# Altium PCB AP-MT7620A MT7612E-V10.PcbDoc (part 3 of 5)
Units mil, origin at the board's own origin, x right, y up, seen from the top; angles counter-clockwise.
Board outline 4645.67 x 3740.16 mil, 4 copper layers (Top, Inner Layer 2, Inner Layer 3, Bottom), stack 35.4 mil thick; 603 components, 409 nets, 1850 pads, 2004 vias.
Unrouted connection lines stored in the file: 90.
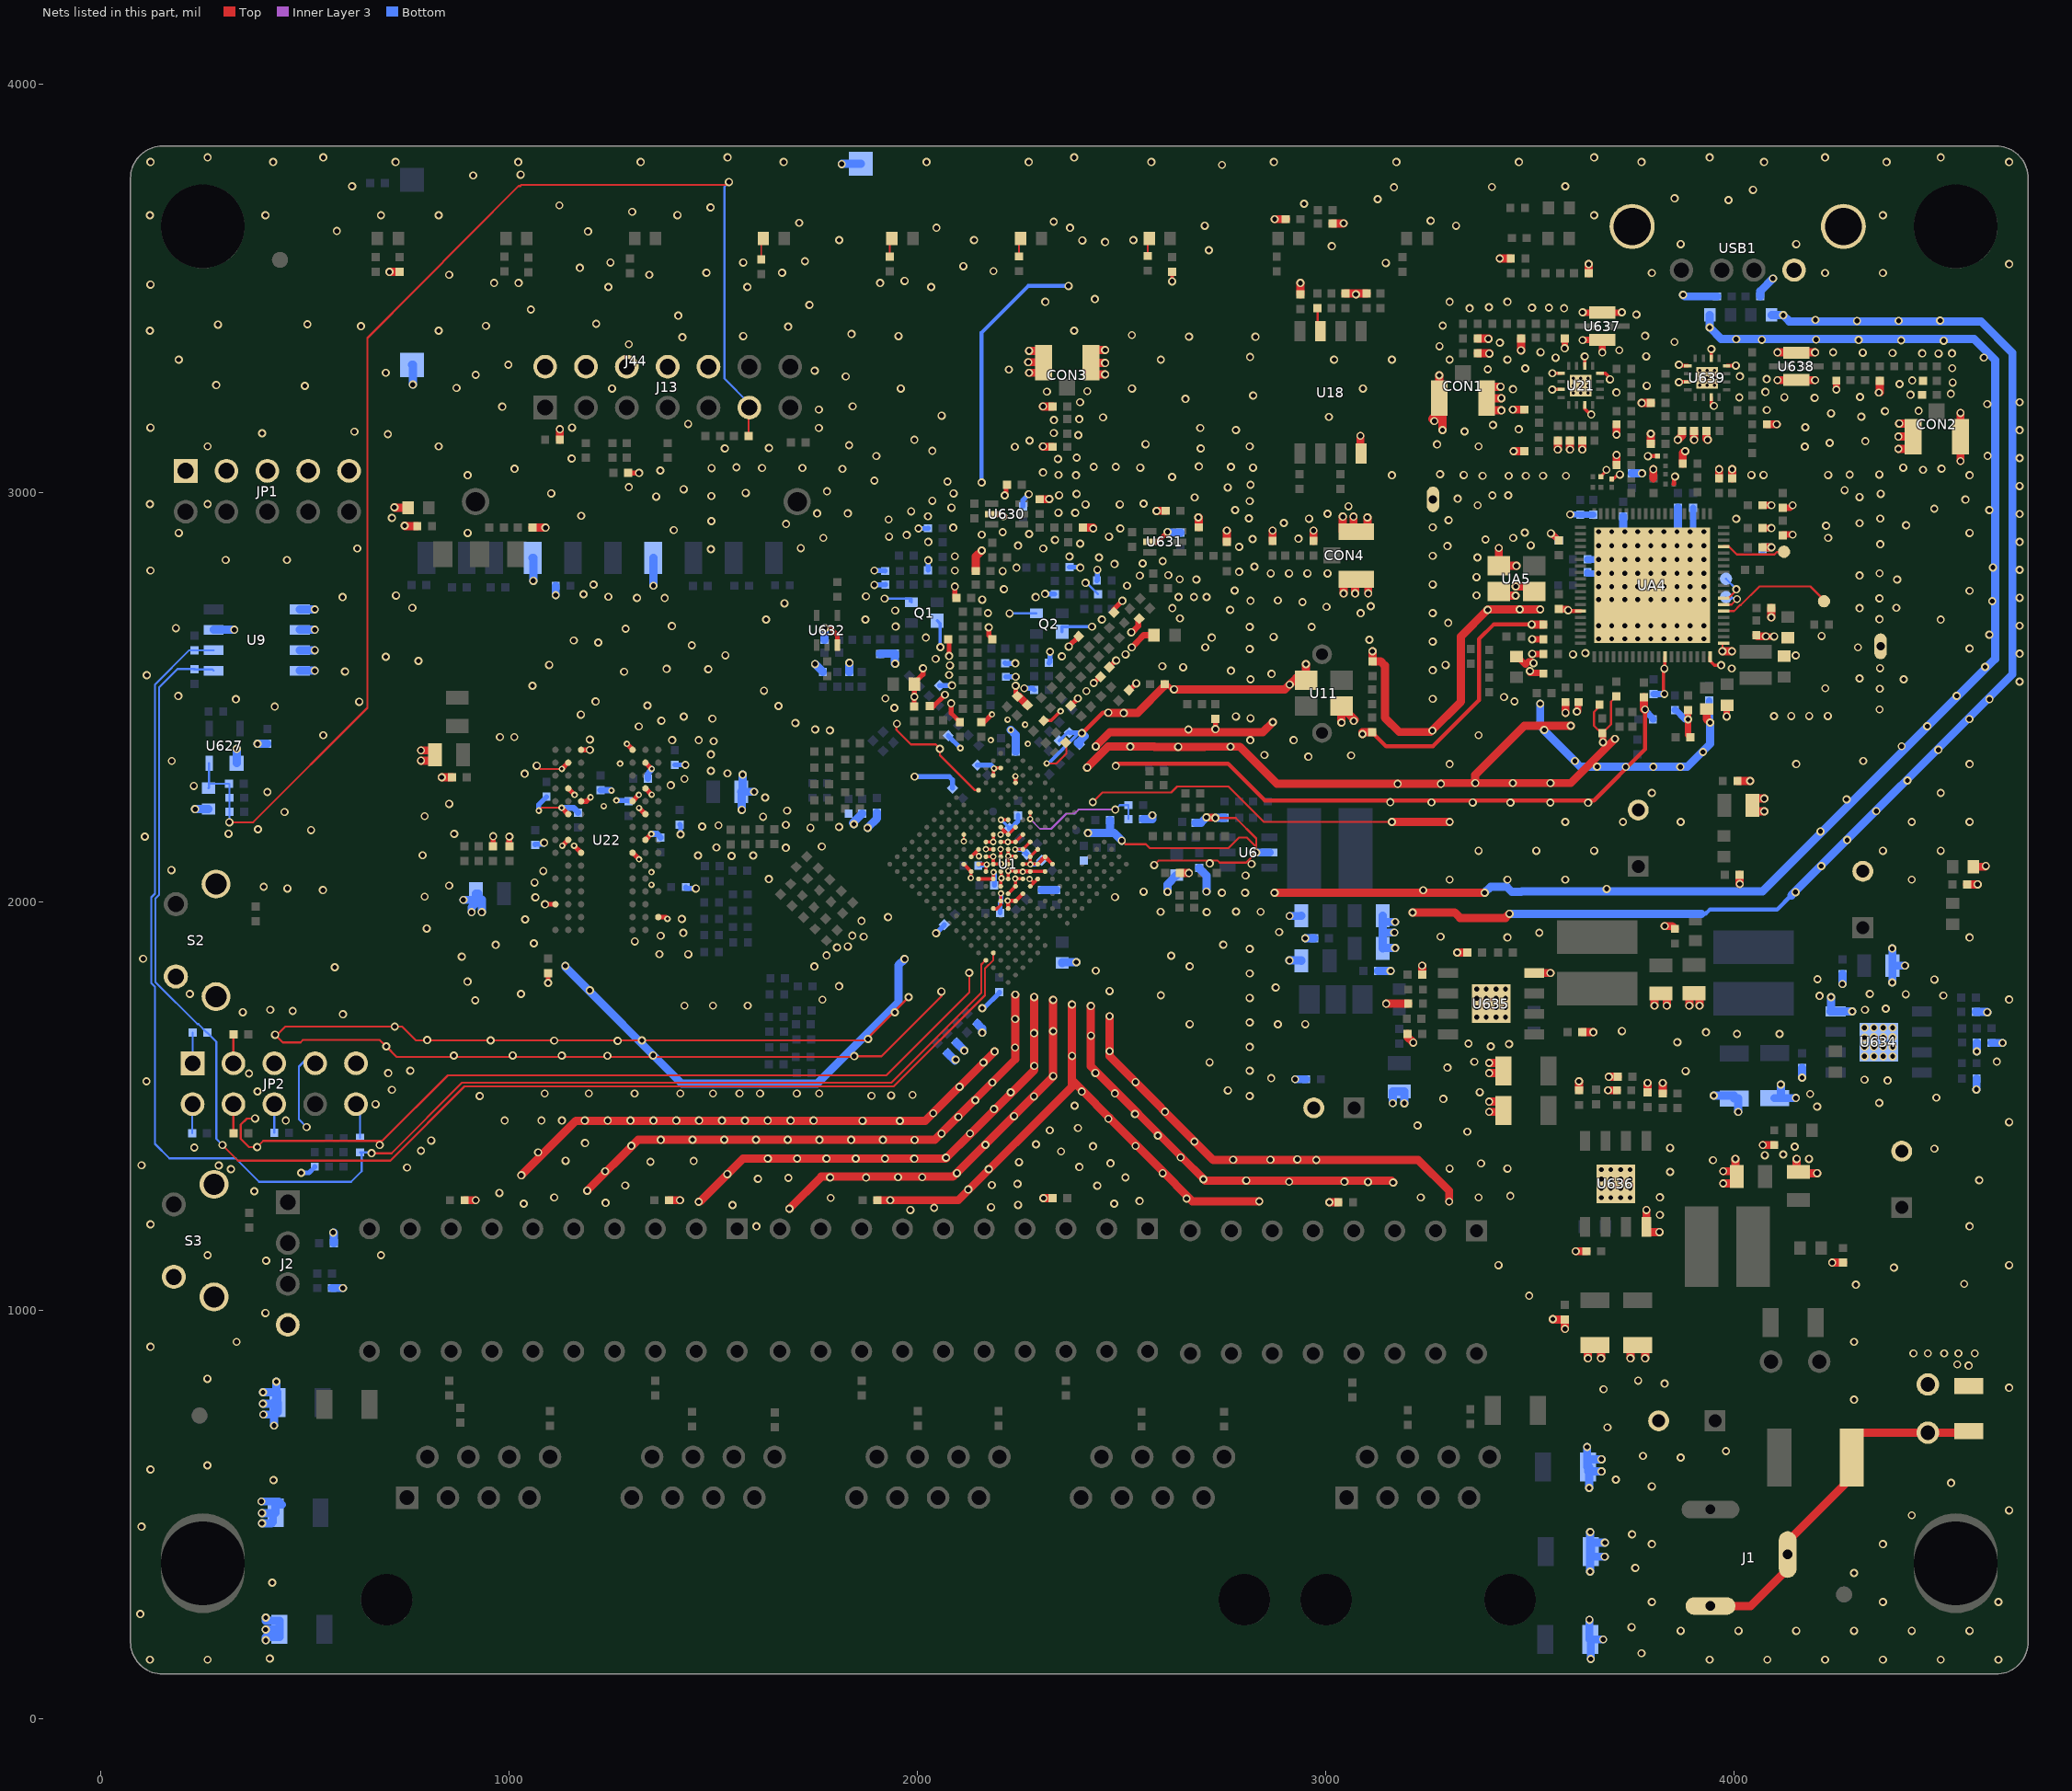
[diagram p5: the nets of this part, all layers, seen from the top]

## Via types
v1: diameter 20, hole 12, Top to Bottom, 1824 vias
v2: diameter 16, hole 8, Top to Bottom, 180 vias

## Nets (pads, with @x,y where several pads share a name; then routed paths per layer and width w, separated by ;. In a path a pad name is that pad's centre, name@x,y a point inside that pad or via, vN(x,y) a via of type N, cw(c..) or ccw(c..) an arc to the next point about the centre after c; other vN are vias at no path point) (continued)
GND: C1.2 C2.2 C7.2 C29.2 C30.2 C32.2 C33.2 C34.2 C36.2 C39.2 C40.2 C41.2 C42.2 C43.2 C44.2 C46.2 C48.2 C50.2 C51.2 C54.2 C55.2 C56.2 C57.2 C58.2 C69.1 C70.2 C72.2 C73.2 C75.2 C76.2 C77.2 C82.1 C83.2 C87.2 C88.2 C90.2 C91.2 C92.1 C93.2 C94.2 C97.2 C99.2 C100.2 C103.2 C104.2 C105.2 C107.1 C108.2 C109.1 C110.2 C111.2 C112.2 C114.2 C115.2 C116.1 C117.1 C118.1 C119.1 C120.1 C121.2 C122.1 C125.2 C128.2 C129.2 C130.2 C131.2 C132.2 C133.2 C134.2 C135.2 C136.2 C137.2 C138.2 C139.2 C140.2 C159.1 C160.1 C161.1 C162.1 C166.2 C167.2 C170.1 C182.1 C210.2 C215.2 C275.2 C456.2 C457.2 C821.2 C841.2 C842.2 C843.2 C844.2 C845.2 C846.2 C847.2 C925.2 C926.2 C928.2 C929.2 C952.2 C963.2 C964.2 C965.2 C966.2 C967.2 C968.2 C969.2 C970.2 C971.2 C973.2 C976.2 C977.1 C978.1 C979.1 C982.1 C985.2 C986.2 C987.2 C988.2 C989.2 C990.2 C991.2 C992.2 C994.2 C995.2 C996.2 C997.2 C999.1 C1000.2 C1001.1 C1004.1 C1005.1 C1007.2 C1008.2 C1016.2 C1017.2 C1018.1 C1019.1 C1020.2 C1021.2 C1022.2 C1025.2 C1026.2 C1027.1 C1028.1 C1029.1 C1030.2 C1031.2 C1032.2 C1033.2 C1035.1 C1037.2 C1038.2 C1039.1 C1040.1 C1041.2 C1042.2 C1043.2 C1045.2 C1046.1 C1048.2 C1049.2 C1051.2 C1052.2 C1061.1 C1062.1 C1063.2 CA15.2 CA16.2 CA19.2 CA20.2 CA22.2 CA24.2 CA28.2 CA32.2 CA34.2 CA35.2 CA36.2 CA37.2 CA38.2 CA39.2 CA40.2 CA41.2 CA42.2 CA43.2 CA44.2 CA45.2 CA47.2 CA48.2 CA49.2 CA50.2 CA51.2 CA52.2 CA53.2 CA54.2 CA55.2 CA56.2 CA57.2 CA58.2 CA59.2 CA60.2 CA61.2 CA62.2 CA63.2 CA64.2 CA67.2 CA68.2 CA69.2 CA70.2 CA71.2 CA72.2 CA73.2 CA74.2 CA75.1 CON1.2 CON1.3 CON2.2 CON2.3 CON3.2 CON3.3 CON4.2 CON4.3 D3.1 D4.1 J2.4 J13.2 J13.4 J13.6 J13.8 J13.10 J44.3 J44.6 J44.GND1 J44.GND2 JP1.1 JP1.3 JP1.5 JP1.7 JP1.9 JP2.5 JP2.7 JP2.9 L6.2 L9.2 L18.1 L36.2 LA11.1 LA12.1 LA13.1 LA14.1 Q1.2 Q1.4 Q2.2 Q2.4 R24.2 R42.1 R51.2 R54.2 R107.2 R126.1 R127.1 R130.1 R131.1 R134.1 R135.1 R139.1 R142.1 R159.1 R161.1 R173.1 R174.1 R176.1 R257.2 R351.2 R381.2 R477.1 R813.2 R825.2 R898.2 R943.2 R945.2 R946.2 R947.2 R950.2 R951.2 RA11.2 RA12.2 RA15.1 RC1.2 S2.2 S2.3 S2.4 S3.2 S3.3 S3.4 SHA1.1 SHA1.2 U1.C2 U1.C4 U1.D2 U1.F2 U1.F6 U1.F7 U1.F8 U1.F9 U1.F10 U1.F11 U1.F12 U1.G6 U1.G7 U1.G8 U1.G9 U1.G10 U1.G11 U1.G12 U1.H6 U1.H7 U1.H8 U1.H9 U1.H10 U1.H11 U1.H12 U1.J6 U1.J7 U1.J8 U1.J9 U1.J10 U1.J11 U1.J12 U1.K4 U1.K6 U1.K7 U1.K8 U1.K9 U1.K10 U1.K11 U1.K12 U1.L6 U1.L7 U1.L8 U1.L9 U1.L10 U1.L11 U1.L12 U1.M6 U1.M7 U1.M8 U1.M11 U1.M12 U1.N11 U6.5 U9.1 U9.2 U9.3 U9.4 U9.7 U11.2 U11.4 U18.4 U21.1 U21.3 U21.7 U21.12 U21.14 U21.17 U22.A3 U22.A7 U22.B2 U22.B8 U22.D2 U22.D8 U22.E3 U22.E7 U22.F2 U22.F8 U22.H2 U22.H8 U22.J3 U22.J7 U22.N1 U22.P9 U627.1 U630.2 U631.2 U632.3 U634.4 U634.9 U635.4 U635.9 U636.4 U636.9 U637.1 U637.3 U638.1 U638.3 U639.1 U639.3 U639.7 U639.12 U639.14 U639.17 UA4.14 UA4.31 UA4.38 UA4.39 UA4.77 UA5.1 UA5.2 UA5.4 UC1.2 UC2.2 USB1.4 USB1.5 USB1.6 | length 45986.2
  Top w4: v1(1068.5,2332.5) 1076.5,2324.5 v2(1130,2324.5) ; v2(1073.5,2222.5) 1080.5,2229.5 v2(1129.5,2229.5)
  Top w5: v1(379,1469) 359,1469 344,1454 344,1419 364,1399 v1(384,1399) 399,1414 674,1414 ; v1(684,1404) 674,1414 ; v1(1950.08,2435.08) 1949,2434 1949,2420 1984.5,2384.5 2045.09,2384.5 v1(2055.59,2374) 2055.59,2357.87 2141,2272.45 U1.F2@2150.12,2272.45 ; v1(1978.72,1766) 1930.36,1717.63 1930.36,1717.36 1873.33,1660.33 1111.32,1660.33 772.67,1660.33 739,1694 v1(721,1694) 453,1694 v1@430.5,1671.5 ; v1(2059.19,1779.88) 2059.19,1768.19 1912.51,1621.51 v1(1845.71,1621.51) 1845.71,1619.77 1009.77,1619.77 725.72,1619.77 v1(700.04,1645.45) 684.49,1661 496,1661 490,1655 447,1655 v1@430.5,1671.5 ; U1.K4@2113.93,2163.88 v2(2114,2147.5) ; v1(2127.24,1825.64) 2127.24,1777.24 1924.5,1574.5 850.7,1574.5 690.2,1414 674,1414 ; v2(2317,2338) 2341,2338 2365,2362 2365,2388 C104.2@2363.73,2388.73 ; v1(2429.89,2243.11) 2453.53,2266.75 2621.75,2266.75 2636.51,2281.51 2762.04,2281.51 2848.65,2194.9 v1(3161.99,2194.9) ; v1(2500.62,2148.92) 2509.4,2140.13 2559.76,2140.13 2568.9,2131 2762.28,2131 2787.78,2156.5 2806.83,2156.5 2830,2133.33 ; C456.2@2578.09,2652 C456.2@2579,2651.09 ; v1(2580.03,2089.45) 2590.59,2100 2735.7,2100 2740.7,2095 2805,2095 v1(2830,2120) 2830,2133.33 ; v1(2729.94,2204.56) 2779.82,2204.56 2830,2154.39 2830,2133.33 ; v1(3593.43,2712.99) 3593.43,2711.85 3623.8,2711.85 UA4.14@3623.8,2711.01 ; RA15.1@3670.36,2481.58 3670.36,2477.36 3657,2464 3657,2430 3675,2412 CA75.1@3677,2412 3698.55,2433.55 3698.55,2489.55 CA70.2@3711,2502 ; 3802,3036 3803,3036 ; v1(3971.13,2612.49) 3971.13,2632.27 UA4.39@3974.2,2632.27 ; v1@430.5,1671.5 430,1671 427,1674 v1(428,1674) v1@430.5,1671.5
  Top w8: U1.M6@2113.93,2091.5 U1.M7@2132.02,2073.4 2131,2072.38 v2(2131,2057.5) ; U1.L6@2132.02,2109.6 2142.21,2119.79 ; U1.M8@2150.12,2055.31 U1.L9@2186.31,2055.31 2186.31,2071.31 v2(2187,2072) ; U1.L7@2150.12,2091.5 2167.5,2091.5 v2(2170,2090.5) 2168.21,2087.21 U1.L8@2168.21,2073.4 ; U1.K6@2150.12,2127.69 2142.21,2119.79 ; v2(2151,2111) 2142.21,2119.79 ; v2(2168,2128) 2168.31,2127.69 U1.J7@2186.31,2127.69 ; U1.K7@2168.21,2109.6 2185.6,2109.6 v2(2186,2110) ; U1.J6@2168.21,2145.79 2185.79,2145.79 v2(2186,2146) 2186.31,2146.31 U1.H6@2186.31,2163.88 ; U1.N11@2186.31,1982.93 2187.24,1982 2194.4,1982 2204.4,1992 U1.M11@2204.4,2001.02 2204.7,2001.02 2204.7,2020 v2(2205,2020) ; U1.K8@2186.31,2091.5 2204.5,2091.5 v2(2205,2092) ; U1.D2@2186.31,2308.64 2186.31,2325.31 v2@2187.94,2325.69 ; v2(2188,2325.7) v2@2187.94,2325.69 ; v2(2204,2128) 2204.4,2127.6 U1.J8@2204.4,2109.6 ; v2(2204,2164) 2213.19,2173.19 ; U1.L10@2204.4,2037.21 2204.4,2055.4 v2(2206,2057) 2206,2071.81 U1.K9@2204.4,2073.4 ; U1.H7@2204.4,2145.79 2221.79,2145.79 v2(2222,2146) 2240.38,2146 U1.G8@2240.6,2145.79 U1.F8@2258.69,2163.88 ; U1.G6@2204.4,2181.98 2213.19,2173.19 ; U1.C2@2204.4,2326.74 2188.99,2326.74 v2@2187.94,2325.69 ; v2(2205,2200) 2222.43,2200 U1.F6@2222.5,2200.07 ; U1.L11@2222.5,2019.12 U1.K11@2240.6,2037.21 2240.6,2055.4 v2(2240,2056) 2258,2056 U1.J11@2258.69,2055.31 ; U1.K10@2222.5,2055.31 v2@2222.5,2074.5 ; U1.J9@2222.5,2091.5 2222.5,2110.5 v2(2223,2111) ; U1.H8@2222.5,2127.69 2222.5,2111.5 v2(2223,2111) ; v2(2223,2075) v2@2222.5,2074.5 ; v2(2240,2127.5) 2240.19,2127.69 U1.G9@2258.69,2127.69 U1.F9@2276.79,2145.79 ; U1.J10@2240.6,2073.4 2239.5,2074.5 v2@2222.5,2074.5 ; U1.H9@2240.6,2109.6 2239.19,2111 v2(2223,2111) ; U1.F7@2240.6,2181.98 U1.G7@2222.5,2163.88 2213.19,2173.19 ; U1.H10@2258.69,2091.5 v2@2276.79,2091.5 ; v2(2275,2055) 2275.5,2055.5 2285.29,2045.71 ; U1.J12@2276.79,2037.21 2285.29,2045.71 ; U1.H11@2276.79,2073.4 U1.G12@2312.98,2073.4 ; U1.H12@2294.88,2055.31 2285.29,2045.71 ; U1.G11@2294.88,2091.5 v2@2278,2091.5 ; U1.F10@2294.88,2127.69 U1.G10@2276.79,2109.6 v2@2276.79,2091.5 ; C842.2@2309.72,2442.62 2310.1,2443 2328,2443 v2(2351,2466) ; v1(3554.64,3253.16) U21.3@3576.26,3253.16 ; v1(3554.87,3293.11) 3554.87,3292.53 U21.1@3576.26,3292.53 ; U21.7@3633.84,3215.26 3633.84,3206.43 3648.39,3191.87 v1(3650.06,3191.87) ; U21.14@3633.84,3310.74 3633.84,3334 v1(3634,3334) ; U21.12@3671.74,3292.53 3685.09,3292.53 3697.81,3279.81 v1(3696,3278) ; C77.2@3674,3040 3674,3040.68 3673.32,3040.68 3688.14,3055.5 v1(3687.17,3056.47) ; L18.1@3700,3034 3701.86,3034 3701.86,3032.14 3717.36,3047.64 v1(3720,3045) ; v1(3829,2508) 3826.6,2510.4 3826.6,2567.6 v1(3829,2570) 3830.38,2570 3830.38,2598.8 UA4.31@3830.5,2598.8 ; v1(3864.82,3313.94) 3864.82,3311.53 U639.1@3886.26,3311.53 ; v1(3864.89,3270.86) 3864.89,3272.16 U639.3@3886.26,3272.16 ; UA4.38@3940.73,2598.8 3940.73,2589.35 3951.76,2578.32 v1(3968.02,2578.32) ; U639.7@3943.84,3234.26 3943.84,3215.53 3946.26,3213.1 v1(3950.26,3213.1) ; U639.14@3943.84,3329.74 3943.84,3351.84 v1(3944,3352) ; U639.12@3981.74,3311.53 4003.53,3311.53 v1(4004,3312) ; v2@2276.79,2091.5 v2@2277.5,2091.5 ; v2@2276.79,2091.5 2276.79,2091.21 v2(2277,2091) ; v2(2277,2091) v2@2278,2091.5 ; v2(2277,2091) v2@2277.5,2091.5 ; v2@2277.5,2091.5 v2@2278,2091.5
  Top w10: v2(2186,2110) 2186,2091.5 U1.K8@2186.31,2091.5 ; U1.M12@2222.5,1982.93 2222.5,2000.97 v2@2221.9,2001.57 ; U1.C4@2240.6,2290.55 v2@2240.55,2306.5 ; U1.J10@2240.6,2073.4 v2@2258.69,2073.4 ; U1.K12@2258.69,2019.12 U1.L12@2240.6,2001.02 2240.6,2001.57 v2@2221.9,2001.57 ; U1.H11@2276.79,2073.4 v2@2260,2073.4 ; U1.G11@2294.88,2091.5 U1.F11@2312.98,2109.6 U1.F12@2331.07,2091.5 ; v1(2403,2412) 2403.63,2411.37 2454.4,2462.13 v1(2467.89,2462.13) ; v1(2486,2332) 2491.5,2337.5 2761.16,2337.5 2851.16,2247.5 3656.5,2247.5 3781.67,2372.67 3781.67,2468 v1(3781.67,2470.04) ; v1(2624,3518) C846.2@2624,3541 ; C1061.1@3113.5,2414 3147.5,2380 3262.42,2380 3375,2492.58 3375,2642.01 3410.99,2678 v1(3504.34,2678) ; v1@3593.43,2711.85 3593.43,2711.01 UA4.14@3623.8,2711.01 ; v1(3788.76,3090) C1063.2@3812,3090 ; 3852,3022 3852.53,3022 3852.53,3040.21 v1(3855.21,3040.21) ; v2@2221.9,2001.57 2221.35,2001.57 v2(2221.35,2002.12) v2@2221.9,2001.57 ; v2@2258.69,2073.4 v2@2260,2073.4 ; v2@2258.69,2073.4 v2(2258.4,2073.12) v2@2260,2073.4
  Top w12: C125.2@961.5,2135.5 961.71,2135.5 v1(961.71,2159.62) ; v1(1088.89,1993.1) 1088.89,1993.22 1114.07,1993.22 U22.N1@1114.07,1993.34 ; v1(1096.5,1801) C132.2@1096.5,1824.5 ; v2(1129.5,2229.5) 1145.19,2213.81 U22.F2@1145.57,2213.81 ; v2(1130,2324.5) 1145.3,2339.8 U22.B2@1145.57,2339.8 ; v2(1131,2136.5) 1145.32,2150.82 U22.H2@1145.57,2150.82 ; U22.D2@1145.57,2276.8 1145.57,2276.43 v2(1161,2261) ; v2(1160,2136.5) 1177.06,2119.44 U22.J3@1177.06,2119.32 ; U22.E3@1177.06,2245.31 1190.31,2245.31 v2(1200,2255) ; U22.A3@1177.06,2371.29 1198.21,2371.29 v1(1198.5,2371) ; v2(1288.92,2385.91) 1288.8,2385.78 1303.17,2371.41 U22.A7@1303.05,2371.29 ; C845.2@1292,3049 v1(1319,3049) ; U22.J7@1303.05,2119.32 1303.18,2119.32 v2(1319,2103.5) ; U22.E7@1303.05,2245.31 1303.05,2245.55 v2(1318.5,2261) ; v2(1319,2229) 1334.19,2213.81 U22.F8@1334.54,2213.81 ; U22.H8@1334.54,2150.82 1334.54,2151.04 v2(1349,2165.5) ; U22.D8@1334.54,2276.8 1334.7,2276.8 v2(1350,2261.5) ; U22.B8@1334.54,2339.8 v2(1350,2324.5) ; U22.P9@1366.04,1961.84 1384.16,1961.84 v2(1388.5,1957.5) ; v1(1774,2669) 1787.09,2669 1804.59,2651.5 U632.3@1804.59,2627.72 ; C109.1@1992.5,2477.5 1992.5,2497 v1(1993,2501) 1993,2532.59 C457.2@1992.59,2533 ; C457.2@1992.59,2532 C457.2@1992.59,2533 ; v1(2014,2571) 2014,2556 1992.59,2534.59 C457.2@1992.59,2533 ; C107.1@2030.5,2478.5 2031,2478 2040,2478 v1(2068,2506) ; C105.2@2075.5,2641.5 2078,2637.31 v1(2078,2601) ; v1(2083,2485) 2083,2461 C844.2@2104.5,2439.5 ; v1(2092,2771) 2092,2743 C99.2@2096,2743 ; C843.2@2156.5,2439.5 2157,2439 2164,2439 v2(2183,2458) ; v1(2175,2671) 2175,2651.5 2183.5,2643 L9.2@2183.5,2641.5 ; U630.2@2182.09,2948.5 2182.09,2947.19 2211,2947.19 v1(2211,2943) ; v1(2214,2994) 2217.6,2994 2217.6,3020 C990.2@2220,3020 ; v1(2241,2528) 2241.07,2526 2241.07,2508.39 2245.23,2504.23 C110.2@2245.23,2502.23 ; v1(2371,2624) 2371,2624.45 L6.2@2395.27,2648.73 ; C82.1@2375.77,2479.23 2393,2496.46 v1(2393,2497) ; v1(2432,2535) 2447.23,2550.23 C92.1@2448.77,2550.23 ; C90.2@2470.23,2573.77 2486.46,2590 v1(2487,2590) ; C87.2@2481.27,2707.73 2481.27,2715.27 v1(2502,2736) ; C83.2@2518.23,2517.23 2518.73,2516.73 v1(2536,2534) ; C88.2@2542.25,2690.75 C88.2@2543.77,2692.27 ; U631.2@2569.09,2880.5 2569.09,2878.91 2586.9,2878.91 v1(2612.6,2904.61) ; C456.2@2579,2651.09 C456.2@2579.91,2652 ; R107.2@2606,2532 2606,2534.41 2608.41,2534.41 2626.1,2516.72 v1(2628.65,2519.27) ; v1(2730,2422) C108.2@2730,2447
  Top w15: R351.2@1001.5,2135.5 v1(1001.54,2158.91) ; v1(2524,2659) 2526,2659 2541,2674 2541,2689.5 C88.2@2542.25,2690.75 ; v1(2525.3,2622) 2526,2622 2554,2652 C456.2@2578.09,2652
  Top w16: CA43.2@3467,2599.59 3469,2599.59 3488.66,2579.93 3489.34,2579.93 3496.66,2587.25 3504.93,2587.25 v1(3508.57,2583.6) ; v1(3500,2564) 3500,2559.2 3533,2559.2 CA74.2@3533,2558 ; v1(3505.49,2642) CA50.2@3533,2642 ; v1(3505.64,2606) CA71.2@3533,2606 ; v1(3551.15,2900.9) 3552.24,2901.99 3570.62,2883.62 3570.62,2884 CA38.2@3571,2884 ; CA44.2@3571,2716 3571,2715.4 3593.43,2715.4 v1(3593.43,2712.99) ; v1(3585,3354) LA13.1@3585,3378 ; v1(3615,2465) 3618.2,2465 3618.2,2488 CA69.2@3619,2488 ; v1(3629,3374) 3629.54,3374.54 U637.1@3677,3374.54 v1(3677,3344) ; v1(3629,3442) 3629.54,3441.46 U637.3@3677,3441.46 3724.46,3441.46 v1(3725,3442) ; CA75.1@3677,2412 3678.6,2412 v1(3678.6,2389.95) ; CA63.2@3887,2468 v1(3887,2446) 3887,2408 CA64.2@3893,2402 ; v1(3981.56,2452.96) 3981.56,2480.41 CA60.2@3983,2480.41 ; CA58.2@4069,2914 v1(4091,2914) ; CA56.2@4069,2970 v1(4091,2970) ; v1(4077.62,2648.97) 4077.62,2648.91 v1(4097.87,2648.86) v1(4097.87,2648.86) ; CA57.2@4119,2896 4119,2898 v1(4143,2898) ; CA55.2@4119,2964 4137,2964 v1(4143,2970) ; v1(4250,3253) CA32.2@4250,3275
  Top w20: v1(708,3541) R159.1@733,3541 ; v1(720,2965) 721,2964 C964.2@753.41,2964 ; v1(745,2920) 746,2919 C963.2@776,2919 ; v1(785,2345) 819.55,2345 C965.2@819.55,2359 819.55,2370 v1(785,2370) ; v1(836,2304) C966.2@861,2304 ; C115.2@892,1269 v1(919,1269) ; v1(1030.8,1329.91) 1164.41,1463.52 1354,1463.52 1522,1463.52 1690,1463.52 1865.97,1463.52 2020.08,1463.52 v1(2189.45,1632.89) ; R898.2@1058,2915 v1(1090,2915) ; R477.1@1125,3130 v1(1125,3156) ; v1(1192.08,1292.41) 1316.34,1416.67 1527.39,1416.67 v1(1838.12,1416.68) 2042.78,1416.67 2240.07,1613.96 v1(2240.07,1772.13) ; C114.2@1392,1269 v1(1419,1269) ; v1(1465,1265) 1465.69,1265.69 1468.36,1265.69 1573.17,1370.5 1821.28,1370.5 2069.38,1370.5 2071.24,1372.35 2130.07,1431.18 2230.39,1531.51 2286.33,1587.45 v1(2286.33,1766.19) ; v1(1687.06,1248.17) 1765.39,1326.5 2087.61,1326.5 2332.73,1571.62 v1(2332.73,1759.21) ; C112.2@1902,1269 v1(1934,1269) 2100.52,1269 2378.75,1547.23 2378.75,1563.14 ; C100.2@2143,2809 2143,2844 v1(2158,2859) ; C110.2@2245.23,2502.23 2248.23,2502.23 C841.2@2269.73,2480.73 ; v1(2272,3320) CON3.2@2307.94,3320 ; v1(2274,3294) 2307.94,3294 CON3.2@2307.94,3320 ; v1(2274,3348) 2307.94,3348 CON3.2@2307.94,3320 ; C1048.2@2300,2984.5 2323,2984.5 v1(2323,2985) ; v1(2308,3114) 2308,3113 C973.2@2331,3113 ; v1(2308,3212) 2308,3211 C991.2@2331,3211 ; v1(2309,1274) C111.2@2331,1274 ; v1(2378.75,1747.88) 2378.75,1563.14 ; C1049.2@2405.48,2915.62 2431,2915.62 v1(2431,2913) ; v1(2416,2328) 2467.17,2379.17 v1(2521.67,2379.17) 2580.04,2379.17 2580.58,2378.63 v1(2638.95,2378.63) 2702.74,2378.63 2703.01,2378.9 v1(2766.79,2378.9) 2790,2378.9 2880.9,2288 v1(3176,2288) v1(3282,2288) 3284,2290 v1(3366,2290) ; v1(2424.92,1744.22) 2424.92,1596.97 2438.79,1583.09 2646.5,1375.38 2704.96,1316.93 3160.62,1316.93 v1(3165.19,1312.36) ; v1(2437.1,2379.85) 2472.04,2414.78 2846.34,2414.78 v1(2870.54,2438.98) ; v1(2460,3290) 2426.06,3290 CON3.3@2426.06,3318 ; v1(2460,3318) CON3.3@2426.06,3318 ; v1(2460,3350) 2426.06,3350 CON3.3@2426.06,3318 ; v1(2467.89,2462.13) 2467.89,2461.76 2505.37,2461.76 v1(2505.37,2461.4) 2539.2,2461.4 2606,2528.2 R107.2@2606,2532 ; v1(2470.98,1719.23) 2470.98,1621.34 2724.96,1367.36 v1(2976.81,1367.36) 3226.75,1367.36 3302.06,1292.05 v1(3302.06,1265.53) ; v1(2586,2956) 2586,2956.5 C1007.2@2608.5,2956.5 ; v1(2628.65,2519.27) 2900.17,2519.27 v1(2911.91,2531.01) 2927.9,2547 U11.4@2951.69,2547 ; C54.2@2643,2070 2665.04,2070 v1(2665.04,2069.67) ; v1(2688,2940) 2689,2940 C1051.2@2689,2916 ; v1(2708,2206.17) 2708,2205.67 2729.94,2205.67 v1(2729.94,2204.56) ; C1052.2@2758,2880 v1(2758,2908) ; v1(2837.32,1266.3) 2673.27,1266.3 2663.14,1276.5 2602.88,1337.24 2536.69,1403.95 2470.51,1470.66 2404.83,1536.85 2378.75,1563.14 ; C971.2@2870,2883 v1(2870,2908) ; v1(2874.73,2021.56) 3141.84,2021.56 3141.94,2021.67 v1(3389.05,2021.67) ; v1(2875,3670) C847.2@2902,3670 C847.2@2903,3670 ; C137.2@2938,3486 v1(2938,3514) ; v1(2951.5,2581) 2951.69,2579 U11.4@2951.69,2547 ; U11.4@2951.69,2541.5 U11.4@2951.69,2547 ; C970.2@2970,2883 v1(2970,2908) ; v1(3009,1264) C121.2@3031,1264 ; R134.1@3017,3659 3043,3659 v1(3044,3660) ; v1(3038.5,2438) U11.2@3038.5,2475.94 ; v1(3042,2942) 3042,2906.11 3042.06,2906.06 CON4.2@3068,2906.06 ; v1(3044,2754) 3044,2787.94 CON4.3@3072,2787.94 ; R127.1@3048,3488 v1@3074,3488 ; v1(3068,2942) CON4.2@3068,2906.06 ; v1(3068.5,2442) 3071.06,2444.56 3039.68,2475.94 U11.2@3038.5,2475.94 ; v1(3072,2754) CON4.3@3072,2787.94 ; v1(3074,3486) v1@3074,3488 ; v1(3085,3140) 3085,3096.2 U18.4@3087,3096.2 ; v1(3090,2410) 3090,2414 C1061.1@3113.5,2414 ; R135.1@3100,3488 v1@3074,3488 ; v1(3102,2940) 3102,2906.06 CON4.2@3068,2906.06 ; v1(3104,2754) 3104,2787.94 CON4.3@3072,2787.94 ; v1(3114.5,2612.38) C1062.1@3114.5,2588 3134.5,2588 3145,2577.5 3145,2450 3180,2415 3256.65,2415 3331,2489.35 3331,2648.83 3396.17,2714 v1(3396.49,2714) 3397.49,2715 v1(3475,2715) v1(3525,2715) ; v1(3147.98,1749.79) 3147.98,1750 C1035.1@3202,1750 ; v1(3161.99,2194.9) v1(3303.42,2194.9) ; C1029.1@3200,1676 3200,1668.88 3214.22,1654.66 v1(3214.33,1654.77) ; v1(3212.66,1973.23) 3315.75,1973.23 3328.97,1960 3440,1960 v1(3450,1970) ; R946.2@3236,1821 3236,1843.15 v1(3236.1,1843.15) ; v1(3266,3176) 3260.64,3181.36 3283.29,3204 CON1.3@3283.29,3232 ; CON1.3@3277.93,3232 CON1.3@3278,3232 ; v1(3278,3288) CON1.3@3278,3232 ; v1(3286,3154) 3286,3232 CON1.3@3283.29,3232 ; v1(3321.78,1875) R947.2@3347,1875 ; CA15.2@3372,3342 3400.41,3342 v1(3400.41,3341.11) ; CA16.2@3372,3378 3398.16,3378 v1(3398.16,3377.08) ; v1(3400,1485) 3434.88,1485 C1026.2@3434.88,1489 3434.88,1510 v1(3400,1510) ; v1(3400,1580) 3434.88,1580 C1025.2@3434.88,1585 3434.88,1605 v1(3400,1605) ; UA5.1@3423.69,2758.5 3423.69,2748.7 v1(3464.85,2748.7) ; v1(3423.69,2865.21) UA5.4@3423.69,2821.5 v1(3466.73,2821.5) ; v1(3426,3574) R142.1@3453,3574 ; v1(3428,3260) 3394.07,3260 CON1.2@3394.07,3232 ; v1(3430,3202) 3400,3202 3394.07,3207.93 CON1.2@3394.07,3232 ; v1(3430,3232) CON1.2@3394.07,3232 ; v1(3458,3204) R173.1@3486,3204 ; v1(3460,3102) R161.1@3486,3102 ; v1(3465.25,2771.15) 3497.66,2771.15 UA5.2@3510.31,2758.5 ; v1(3477.98,3348.98) CA28.2@3478,3378 ; v1(3504.34,2678) CA39.2@3533,2678 ; U635.4@3510.61,1825 v1(3550,1825) ; v1(3556,978) 3556,977 C2.2@3585,977 3585,954 v1(3586,954) ; v1(3568,3106) C159.1@3568,3128 ; v1(3587,2462) CA67.2@3587,2488 ; v1(3598,3106) C160.1@3598,3128 ; v1(3600,2430) 3486,2430 3366,2310 v1(3366,2290) ; v1(3612,1144) C1039.1@3638,1144 ; C1040.1@3620,1538 v1(3620,1560) ; C1028.1@3628,1680 3654.35,1680 3654.4,1680.05 3654.95,1680.05 v1(3655,1680) ; v1(3628,3106) C170.1@3628,3128 ; v1(3642,882) 3642,913.88 C1038.2@3659,913.88 3674,913.88 v1(3674,882) ; R825.2@3644,3538 v1(3644,3560) ; v1(3691,1538) C1046.1@3713,1538 ; v1(3693,1571) R950.2@3715,1571 ; v1(3708,2398) 3600,2290 v1(3550,2290) v1(3458,2290) v1(3366,2290) ; LA12.1@3712,3068 v1(3712,3092.9) ; v1(3712,3142.83) CA24.2@3712,3168 ; v1(3746,882) 3746,913.88 C1037.2@3764,913.88 3782,913.88 v1(3782,882) ; v1(3773.73,3220) R176.1@3796,3220 ; CA62.2@3779.26,2499.93 3779.26,2470.41 v1@3781.67,2468 ; v1(3785,1245) U636.4@3785,1203.39 3785,1190.89 3785.11,1191 v1(3817,1191) ; R951.2@3788,1533 v1(3788,1556) ; R174.1@3796,3120 v1(3796,3145.12) ; 3802,3036 v1(3802,3058) ; v1(3805,1745) 3805,1774.55 C1030.2@3821,1774.55 3835,1774.55 v1(3835,1745) ; C1043.2@3825,1530 v1(3825,1556) ; v1(3830,1940) 3848,1940 C1032.2@3855,1933 ; v1(3862,3130) 3872,3140 C161.1@3872,3152 ; LA11.1@3874,3072 3874,3097.93 v1(3880,3102) ; v1(3890,1745) 3890,1775.55 C1031.2@3902,1775.55 3915,1775.55 v1(3915,1745) ; v1(3902,3130) C162.1@3902,3152 ; C182.1@3932,3152 3932,3133 v1(3935,3130) ; CA68.2@3932.54,2471.63 3932.54,2446.46 v1(3941,2438) ; CA53.2@3963,3036 v1(3963,3058) ; v1(3971.13,2612.49) v1(3994.45,2612.49) ; v1(3973,1310) 4006.55,1310 C1042.2@4006.55,1327 4003,1330.55 C1042.2@4003,1340 ; v1(3973,1340) C1042.2@4003,1340 ; CA52.2@3995,3036 v1(3995,3058) ; v1(4003,1370) C1042.2@4003,1340 ; C926.2@4008,2295 v1(4039.1,2295) ; C928.2@4013,2065 4013,2042.81 v1(4013.67,2042.81) ; CA36.2@4054.14,2651.56 4056.73,2648.97 v1(4077.62,2648.97) ; CA49.2@4069,2867 v1(4091,2867) ; v1(4070,1404) C952.2@4098,1404 ; v1(4073.5,2220.71) 4044.45,2220.71 C925.2@4044.45,2235 4044.45,2251.99 v1(4073.65,2251.99) ; CA22.2@4080,3168 v1(4104,3168) ; v1(4090.68,2695.49) CA73.2@4090.68,2717.93 ; v1(4106,3276) U638.1@4152,3276 ; v1(4106,3344) U638.3@4152,3344 ; U638.1@4152,3276.54 U638.1@4152,3276 ; U638.3@4152,3343.46 U638.3@4152,3344 ; v1(4153,1370) 4153,1342.45 C1041.2@4157,1338.45 4160.45,1335 v1(4203,1335) ; v1(4198,3276) U638.1@4152,3276 ; v1(4198,3344) U638.3@4152,3344 ; v1(4240,1116) C929.2@4266,1116 ; v1(4354.26,3245.76) 4356,3245.76 LA14.1@4356,3274 ; v1(4402,3108) 4436,3108 4440,3104 4440,3135.93 CON2.3@4437.93,3138 ; v1(4402,3138) CON2.3@4437.93,3138 ; v1(4404,3170) 4430,3170 4437.93,3162.07 CON2.3@4437.93,3138 ; v1(4554,3078) 4554.07,3078.07 CON2.2@4554.07,3138 4554.07,3195.93 v1(4554,3196) ; C968.2@4570,2042 v1(4596,2042) ; C967.2@4585.59,2085 4614,2085 v1(4616,2087) ; U11.2@3038.5,2475.94 3038.31,2475.94 U11.2@3038.31,2478.5 3038.5,2478.31 U11.2@3038.5,2475.94 ; CON1.3@3278,3232 CON1.3@3283.29,3232
  Bottom w5: v1(505,1448) 486,1467 486,1596 504,1614 516,1614 JP2.7@526,1604 ; v1(2412,2780) 2414.5,2780 C1000.2@2442.5,2752
  Bottom w5.5: v1(1920,2741.5) 1980.72,2741.5 Q1.4@1980.82,2741.4 ; v1(2226,2705) 2290.91,2705 Q2.4@2291.5,2705.59 ; Q1.4@1980.82,2741.4 1985.5,2741.4 1986,2740.89 Q1.4@1986,2732.59 1981.79,2735.01 Q1.4@1980.82,2741.4
  Bottom w7.87: Q1.2@2049,2687.32 2056.46,2679.85 v1(2056.46,2622.6) ; Q2.2@2354.5,2660.32 2354.5,2672.6 v1(2427.72,2672.6)
  Bottom w8: C72.2@2149.5,2087.5 2168.5,2087.5 v2(2170,2090.5) ; v2(2205,2200) 2205.5,2200 C44.2@2225.77,2179.73 ; v2(2317,2338) 2321,2338 2395,2412 v1@2395,2413.27 ; C94.2@2347.73,2393.73 2370,2416 C994.2@2372.73,2413.27 ; CA41.2@3623,2947 CA41.2@3623,2947.33
  Bottom w10: v1(2157.7,3025.71) 2157.7,3392.57 2271.66,3506.53 v1(2370.39,3506.53) ; v2(2277,2091) 2291.14,2091 2303.07,2102.93 C39.2@2304.77,2101.23 ; 3920,1970 3930,1970 3940,1980 4105,1980 4140,2015
  Bottom w12: v1(492,1336) 511,1336 525,1350 C976.2@525,1351 ; C129.2@1064.5,2138.5 1064.5,2140.62 1086.64,2140.62 v1(1086.64,2143.79) ; v2(1073.5,2222.5) 1073.5,2237.5 C138.2@1092.5,2256.5 ; v2(1263.5,2247.5) 1291.5,2247.5 C133.2@1293.5,2245.5 ; C134.2@1406.5,2334.5 v1(1432.5,2334.5) ; C135.2@1418.5,2188.5 1420.5,2186.5 v1(1420.5,2164.5) ; C130.2@1433.5,2035.5 1433.5,2032 v1(1458,2032) ; v1(1895,2775) 1922,2775 C979.1@1922,2776 ; v1(1895,2810) 1921.5,2810 C988.2@1921.5,2809 ; v1(1993.51,2305.84) 2078.31,2305.84 2086.27,2297.87 C75.2@2086.27,2277.73 ; v1(2003,2913) 2026,2913 C989.2@2026.5,2913.5 ; C985.2@2026,2810.5 2027,2811.5 v1(2027,2835) ; v1(2046.03,1922.29) 2066.64,1942.9 C76.2@2066.27,1943.27 ; C986.2@2054.73,2528.73 v1(2085,2529) ; C215.2@2074.73,1628.27 2078.73,1628.27 v1(2094,1613) ; C987.2@2075.77,2405.77 2105.5,2376.04 v2(2105.5,2375.5) ; C93.2@2146.77,2334.23 2180.77,2334.23 v2(2188,2325.7) ; v1(2159,1739) 2164,1739 2163.49,1739.51 2201.49,1777.51 2201,1777.51 R42.1@2201,1778 ; v2(2187,2072) 2188.5,2070.5 C43.2@2188.5,2039.5 ; C41.2@2203,1972 2203,1996 2205,1998 v2(2205,2020) ; C1001.1@2215,2583.5 2215.5,2583 v1(2240,2583) ; C1004.1@2217,2550 v1(2241,2550) ; C44.2@2225.77,2179.73 2229.73,2179.73 2247,2197 C91.2@2247,2211 ; v2(2240,2127.5) 2256.55,2127.5 C40.2@2268.15,2115.89 ; C992.2@2259,2967 2259,2983 v1(2273,2997) ; v1(2262,2522) 2282.5,2522 C995.2@2286.5,2518 ; v1(2313,2753) 2335.5,2753 C999.1@2336.5,2752 ; C1005.1@2322.5,2584 2325,2586.5 v1(2325,2611.5) ; C997.2@2372.5,2818.5 2397.5,2818.5 v1(2399,2817) ; C994.2@2372.73,2413.27 2395,2413.27 2401.73,2413.27 v1(2403,2412) ; C996.2@2440,2785.5 2441,2786.5 v1(2441,2812)
  Bottom w15: v2(1129.5,2229.5) 1158.5,2229.5 1169.5,2218.5 C131.2@1169.5,2217.5 ; C140.2@1224.5,2272.5 1250.5,2272.5 v2(1251.5,2271.5) ; C128.2@1340.5,2300.5 1340.5,2312.5 v2(1350,2324.5) ; v2(1349,2165.5) 1363.5,2165.5 1371.5,2157.5 C139.2@1371.5,2156.5 ; v1(3551.15,2900.9) 3552.15,2901.91 3570.53,2883.53 3571,2883.53 CA40.2@3571,2884 ; v1(3598.62,2947.33) CA41.2@3623,2947.33 ; CA41.2@3623,2947 CA42.2@3655,2947
  Bottom w16: CA34.2@3641,2806 3641,2803 v1(3668,2803) ; CA35.2@3641,2838 3641,2837 v1(3668,2837) ; v1(3781.67,2470.04) 3780.51,2468.87 3802.19,2447.19 3802.19,2446 CA61.2@3801,2446 ; RA11.2@3803,2508 v1(3829,2508) ; RA12.2@3855,2468 3855,2469.31 3856.31,2469.31 3879.61,2446 v1(3887,2446) ; v1(3892,2905) 3899,2912 CA59.2@3899,2964 ; CA72.2@3939,2492 3939,2466 3941,2464 v1(3941,2438)
  Bottom w20: v1(232,2226) 264.59,2226 RC1.2@265,2226.41 ; U9.7@277.49,2665 v1(328,2665) ; U627.1@333.92,2338.68 334,2338.76 v1(334,2374) ; v1(385,2386) C969.2@409,2386 ; v1(394.52,531.66) 436.82,531.66 444.63,523.86 428.88,523.86 C117.1@428.88,504 C117.1@427.67,502.78 ; v1(395.89,478.02) 419.04,478.02 422.53,481.51 422.53,497.65 C117.1@427.67,502.78 ; v1(395.89,503.1) 396.2,502.78 C117.1@427.67,502.78 ; v1(398.06,770.88) C116.1@425.38,770.88 ; v1(398.53,798.82) C116.1@430.86,798.82 ; v1(399.24,744.37) C116.1@425.38,744.37 ; v1(404.84,218.09) C120.1@438.88,218.09 ; v1(404.98,247.54) 404.98,239.49 438.88,239.49 C120.1@438.88,219 C120.1@438.88,218.09 ; v1(405.13,191.98) 405.13,199.61 438.88,199.61 C120.1@438.88,218.09 ; v1(425.38,717.3) C116.1@425.38,744.37 ; v1(430.86,824.99) C116.1@430.86,798.82 ; U9.4@488.51,2565 v1(525,2565) ; U9.3@488.51,2615 v1(525,2615) ; U9.2@488.51,2665 v1(525,2665) ; U9.1@488.51,2715 v1(525,2715) ; R139.1@567,1054 v1(594,1054) ; v1(570,1190) 572,1190 R54.2@572,1164 ; J44.GND1@763.17,3313.44 765,3313.44 v1(765,3265) ; v1(889,2004) 919.55,2004 C73.2@919.55,2019 ; v1(909,1974) 909,1985.78 925.38,2002.17 C73.2@925.38,2013.17 ; v1(934,1974) 934,2004.55 C73.2@925.38,2013.17 ; J44.6@1058.45,2841 1060,2841 v1(1060,2785) ; v1(1115,2750) C275.2@1115,2773 ; v1(1138.5,1842.5) 1138.5,1839.5 1424,1554 1754.8,1554 1954,1753.2 1954,1844 v1(1969,1859) ; J44.3@1353.72,2841 1354.26,2841 v1(1354.26,2773.03) ; v1(1570.5,2224.5) 1570.5,2266.95 C136.2@1568.95,2268.5 ; v1(1572.5,2310.5) 1572.5,2272.05 C136.2@1568.95,2268.5 ; v1(1600.5,2268.5) C136.2@1568.95,2268.5 ; v1(1749.79,2581.21) R131.1@1769,2562 ; C978.1@1773,2641 1773,2668 v1(1774,2669) ; v1(1815,3805) 1815.57,3805.57 J44.GND2@1861.6,3805.57 ; R130.1@1834,2562 v1(1834,2584) ; v1(1845.06,2189.15) 1842.1,2192.1 1848.5,2198.5 C70.2@1865.5,2215.5 ; v1(1878.41,2180.16) 1901.5,2203.25 R813.2@1901.5,2217.5 ; C977.1@1909,2606 1909,2607 C982.1@1945,2607 1945,2582 v1(1946,2582) ; C215.2@2074.73,1628.27 2092,1611 v1(2094,1613) ; C57.2@2096.27,1654.27 2115.27,1635.27 v1(2115,1635) ; C58.2@2147.73,1700.27 2159,1689 v1(2159,1679) ; v2(2229,2420) 2241,2408 C103.2@2241,2400 C97.2@2241,2367.5 ; C167.2@2305,2028 C166.2@2340,2028 ; C42.2@2355,1849.41 2355,1851.58 v1(2389.47,1851.58) ; C36.2@2396.73,2384.73 2393.3,2388.16 2410.07,2404.93 v1(2403,2412) ; v1(2417.81,2167.53) 2417.81,2168 C69.1@2440,2168 R51.2@2472,2168 ; R381.2@2472,2199 R51.2@2472,2168 ; v1(2500.62,2148.92) 2500.62,2148.97 2481.59,2168 R51.2@2475,2168 R51.2@2472,2168 ; R126.1@2553,2202 2575.6,2202 v1(2575.6,2211.08) ; v1(2612.6,2904.61) 2612.6,2903 C1008.2@2644,2903 ; v1(2612.8,2024.14) 2612.8,2042.21 C30.2@2635,2064.41 ; C51.2@2681,2193 2694.83,2193 v1(2708,2206.17) ; C29.2@2690,2082 2708.18,2063.82 v1(2708.18,2024.33) ; v1(2729.94,2204.56) 2729.94,2205 R24.2@2752,2205 ; v1(2830,2120) U6.5@2862.18,2120 ; v1(2911.41,1855.75) 2940.55,1855.75 C56.2@2940.55,1855 ; v1(2911.5,1964.57) 2940.55,1964.57 C33.2@2940.55,1965 ; v1(2925,1565) C50.2@2952,1565 ; v1(2949.89,1910.24) 2949.89,1910 C32.2@2972,1910 ; C55.2@3128,1830 v1(3158.93,1830) ; C34.2@3139.45,1885 C34.2@3139.45,1886 ; C46.2@3139.45,1965 C46.2@3139.45,1950 ; v1(3164.06,1506.5) 3164.06,1535.55 C48.2@3180,1535.55 3192.61,1535.55 v1(3192.61,1506.3) ; v1(3168,1924) 3139.45,1924 ; v1(3170,1886) C34.2@3139.45,1886 ; v1(3170,1950) C46.2@3139.45,1950 ; v1(3389.05,2021.67) 3403.39,2036 3443.41,2036 3455.58,2023.83 3478.83,2023.83 3480,2025 4070,2025 4638.75,2593.75 4638.75,3325.23 4621.87,3342.11 4587.38,3376.6 3968.4,3376.6 v1(3940,3405) 3940,3436 D3.1@3940.41,3436 ; v1(3450,1970) 3920,1970 ; v1(3525,2484) 3525,2430 v1(3535,2420) 3534.14,2419.14 3609.64,2343.64 3623.28,2330 3885.39,2330 3941,2385.61 v1(3941,2438) ; v1(3640,665) C122.1@3640,635 ; v1(3645,565) C122.1@3645,605 ; v1(3645.66,241.93) 3645.66,194.11 C118.1@3647.6,194.11 ; v1(3647.06,360.07) 3647.06,409 C119.1@3647.43,409 ; v1(3647.43,456.62) C119.1@3647.43,409 ; v1(3648.87,146.2) C118.1@3648.87,193.97 ; v1(3675,605) C122.1@3645,605 ; v1(3675,635) C122.1@3642.12,635 ; v1(3679.3,193.97) C118.1@3648.87,193.97 ; v1(3682.88,396.44) 3649.12,396.44 C119.1@3649.12,409 ; v1(3683.45,430.95) 3649.12,430.95 C119.1@3649.12,409 ; CA54.2@3728,2942 3728,2909 v1(3732,2905) ; CA45.2@3750,3048 3774.21,3048 v1(3774.21,3047.74) ; v1(3860,2905) 3862,2905 CA51.2@3862,2964 ; v1(3875,3485) 3879,3481 UC1.2@3958,3481 ; v1(3950,1525) 4000,1525 C1016.2@4000,1517.88 4010,1517.88 v1(4010,1485) ; UC2.2@4064,3481 4064,3494 v1(4095,3525) ; CA48.2@4069,2862 4069,2867 v1(4091,2867) ; D4.1@4091.59,3436 4091.59,3435 v1(4120,3435) 4135,3420 4604.08,3420 4681.25,3342.83 4681.25,2556.25 4140,2015 ; C1017.2@4099,1518.88 C1017.2@4114,1518.88 ; v1(4114,1552) C1017.2@4114,1518.88 ; v1(4151,1519) 4146,1518.88 C1017.2@4114,1518.88 ; v1(4166,1569) C1018.1@4166,1593 ; v1(4237,1766) 4237,1732.11 4235.89,1731 U634.4@4248.39,1731 v1(4289,1731) ; v1(4265,1798) C1022.2@4265,1822 ; v1(4387,1802) 4387.45,1802 C1020.2@4387.45,1843 ; v1(4387,1885) 4387.45,1885 C1020.2@4387.45,1843 ; v1(4418,1843) C1020.2@4387.45,1843 ; R945.2@4592,1730 4618.5,1730 v1(4619.5,1729) ; v1(4593,1540) 4593.5,1540.5 C1019.1@4593.5,1566.5 ; v1(4594,1633) C1027.1@4594,1655 ; R943.2@4630,1654 v1(4657,1654) ; C116.1@425.38,744.37 428.59,744.37 434.45,750.23 434.45,773.43 C116.1@433.88,774 ; C116.1@425.38,744.37 C116.1@425.38,770.88 ; C116.1@425.38,770.88 433.88,770.88 C116.1@433.88,774 ; C116.1@425.38,770.88 425.38,774 C116.1@430.86,774 ; C116.1@430.86,774 C116.1@430.86,798.82 ; C116.1@430.86,774 C116.1@433.88,774 ; C116.1@430.86,798.82 433.88,798.82 C116.1@433.88,774 ; C73.2@919.55,2019 C73.2@925.38,2013.17 ; C73.2@919.55,2019 925.38,2019 C73.2@925.38,2013.17 ; C34.2@3139.45,1886 3139.45,1924 ; 3139.45,1924 C46.2@3139.45,1950 ; C122.1@3640,635 C122.1@3642.12,635 ; C122.1@3640,635 3640,616 C122.1@3642.12,616 ; C122.1@3642.12,616 3645,616 C122.1@3645,605 ; C122.1@3642.12,616 3642.12,605 C122.1@3645,605 ; C122.1@3642.12,616 C122.1@3642.12,635 ; C119.1@3647.43,409 C119.1@3649.12,409 ; C118.1@3647.6,194.11 3648.87,194.11 C118.1@3648.87,193.97 ; C118.1@3647.6,194.11 3647.6,193.97 C118.1@3648.87,193.97
  other v1: 121.44,144.29 262.86,144.29 3939.81,144.29 4081.23,144.29 4222.66,144.29 4364.08,144.29 4505.5,144.29 4646.92,144.29 415,147 3773,160 3869.1,215 4010.52,215 4151.94,215 4293.37,215 4434.79,215 4576.21,215 3748.86,224.08 98,256 3798.39,285.71 4364.08,285.71 4646.92,285.71 421,333 4293.37,356.42 3757.96,369 3798.39,427.13 4364.08,427.13 3750.08,451.01 101,470 4434.79,497.84 4673,510 3798.39,568.55 4531,577 424,584 3710.31,584.93 123,610 262,620 3869.1,639.26 3776.59,642.93 3980,655 3689.64,712.92 4293.37,780.69 3680.09,806.23 4673,810 3829.6,820.02 3764.92,827.44 262,832 4574,864 4546,867 4439,894 4474,894 4514,894 4549,894 4589,894 123,910 333.57,922.11 4293.37,922.11 404.28,992.82 3498,1035 4298,1062 4563,1064 4391,1104 3423,1110 4673,1110 406,1121 262.86,1134.24 687.12,1134.24 1606.36,1204.95 4576.21,1204.95 123,1210 3818,1233 1983.12,1245 2041.45,1250.27 2180.6,1251.91 1547.74,1257.26 2246.99,1257.44 1036.8,1260.43 2482.06,1260.58 1236.99,1262.5 2544.42,1266.85 2659.47,1272.86 1788.09,1274.49 3675,1275 3698,1275 3722,1275 3745,1275 1111.39,1275.66 3232.71,1275.66 3374.13,1275.66 3818,1276 3451.97,1279.24 977.17,1286.74 377,1291 2125,1295 3675,1298 3698,1298 3722,1298 3745,1298 2440.81,1304.46 1285.07,1304.98 2182.51,1306.02 2245.48,1309.08 2910.54,1313.95 3045.8,1314.21 3103.58,1313.69 2805.6,1317.06 4600,1318 2700.55,1320.29 1609.98,1321.32 3675,1321 3698,1321 3722,1321 3745,1321 1684.59,1323.49 1874.65,1324.48 1786.81,1324.66 1952.92,1325.24 2011.99,1325.16 2509.75,1324.51 1535.01,1332.96 2097.11,1335.1 2600.79,1335.17 3843,1338 1236,1340 3675,1344 3698,1344 3722,1344 3745,1344 320,1345 2175,1345 3303.42,1346.37 3444.84,1346.37 751,1349 2396.93,1350.32 101,1354.5 290,1354 2472.94,1359.3 3380.09,1359.04 2249.11,1362.2 1346.85,1362.8 1139.1,1365.49 1452.76,1364.99 3948,1367 2773.27,1368.12 2864.53,1368.12 2930.37,1368.97 4183,1370 1634.22,1370.95 1705.91,1370.95 1777.6,1370.95 1849.29,1370.95 1920.91,1370.88 1992.75,1370.59 2070.47,1373.11 2644.74,1373.62 4075,1379 4120,1381 1072,1386 2352.06,1388.27 785,1390 4490,1395 3843,1397 230,1398 4148,1400 2430.16,1400.94 1300,1402 2534.47,1401.74 2167.04,1404.43 2290.69,1405.75 1186.62,1408.69 2678.58,1412.58 810,1415 1993.49,1416.46 1372.17,1416.56 1449.78,1416.83 1527.39,1417.11 1605.07,1417 1682.75,1416.9 1760.44,1416.79 1915.8,1416.57 2588.92,1426.94 2059.33,1431.86 2129.18,1432.07 3346.63,1436.8 2324.67,1440.07 2393.56,1445.78 3224.74,1451.77 4673,1460 1957.49,1463.3 454,1464 990,1464 1080,1464 1130,1464 1186,1464 1242,1464 1298,1464 1354,1464 1410,1464 1466,1464 1522,1464 1578,1464 1634,1464 1690,1464 1746.23,1463.88 1865.97,1463.57 2468.15,1468.32 2100.78,1472.83 2237.07,1474.71 2533.1,1480.07 2039.04,1481.66 2606.55,1485.25 2187.98,1492.11 4203,1498 2385.34,1500.26 674,1504 4355,1507 2142.23,1513.8 3287.73,1516.79 4495,1520 2285.72,1523.12 929,1524 1888.04,1524.43 2814,1524 1936.2,1525.42 1988.37,1526.67 4186,1529 1088,1530 1196,1530 1308,1530 1420,1530 1500,1530 1565,1530 1615,1530 1705,1530 1760,1530 2483.81,1530.33 2228.96,1532.94 3377.07,1533.18 385,1535 2402.85,1534.89 2760.37,1537.7 714,1539 2103.56,1546.42 2183.85,1557.03 2534.52,1557.92 113,1560 4375.5,1562 4319,1564 2866.61,1567.5 2332.74,1572.61 364,1579 705,1580 2436.32,1580.62 3881,1585 759,1586 2814,1586 3297.89,1593.33 2286.47,1597.55 2162.17,1606.19 2715.67,1606.36 3363.8,1607.71 4643,1608 4319,1621 4342,1621 4365,1621 4388,1621 1241.54,1622.38 2379.09,1622.11 865.7,1622.83 1009.77,1623.35 1129.8,1622.81 1353.27,1623.25 2471.03,1633.59 2239.41,1642.62 2814,1644 4319,1644 4342,1644 4365,1644 4388,1644 3403.99,1645.57 3448.87,1651.03 3349.36,1652.2 3860.89,1655.69 1266.62,1658.99 955.82,1660.25 1111.32,1659.52 1325.82,1660 800.31,1660.98 1879.43,1663.51 4319,1667 4342,1668 4365,1668 4388,1668 2425.16,1671.6 4007,1676 4111,1676 2286,1677.75 3931,1680 2332.68,1682.54 3725.33,1683.07 4319,1691 4342,1691 4365,1691 4388,1691 2667.02,1699.92 2882.81,1699.65 2949.86,1699.92 2814,1704 2239.76,1712.56 3370,1717 3393,1717 3417,1717 3440,1717 594,1724 349,1729 1945.08,1728.87 471,1732 416,1735 4320,1735 4371,1738 3370,1740 3393,1740 3417,1740 3440,1740 1430,1745 1500,1745 1585,1745 918,1758 1767.92,1759.79 4673,1760 3370,1763 3393,1763 3417,1763 3440,1763 2814,1764 4209,1769 4512,1770 2596.31,1770.64 4420,1773 219,1774 1030,1774 4332,1774 2470.85,1780.87 1198.5,1782.5 3370,1786 3393,1786 3417,1786 3440,1786 2877.62,1789.69 1808.55,1792.6 899,1804 4490,1809 4204,1810 2814,1824 2436.99,1830.6 574,1839 1748,1841 2667.02,1841.35 105,1860 885,1865 2621.71,1867.35 1778,1868 1368.7,1871.2 1439.33,1871 2814,1884 1803.5,1887.5 1830,1890 968,1894 2749.19,1894.17 1061.5,1897.5 1308.5,1902.5 3444.84,1912.06 4576.21,1912.06 1869,1914 3280.97,1914.05 1371.82,1916.15 1841,1916.5 1427.23,1923.25 3522.71,1923.45 2885.93,1925.28 799,1934 1863.5,1952.5 1040.12,1956.21 1423.5,1957.5 1928.5,1962 2708.77,1974.08 2595.78,1974.74 2780.53,1975.47 2840.75,1974.67 1065.1,2010.34 2483.99,2010.68 794,2012 2745.86,2021.57 2802.66,2021.56 4150.08,2022.92 2554,2024 545,2028 3238.45,2027.62 3687.63,2030.72 458,2032 400,2036 854,2039 1063.24,2046.53 3303.42,2053.48 3444.84,2053.48 3586.26,2053.48 4434.79,2053.48 1636.67,2054.9 2803.69,2063.84 1084.41,2074.7 174,2077 4213.26,2086.74 2818.41,2091.8 2715.83,2093.26 1463.5,2112.5 1545.5,2111.5 1598.5,2112.5 789.03,2113.27 3374.13,2124.19 3515.55,2124.19 3656.97,2124.19 4364.08,2124.19 4505.5,2124.19 1508.5,2132.5 1678.5,2131.5 1766.5,2134.5 4276.45,2150.55 109,2159 314,2166 866.5,2165.5 4211.22,2171.45 516,2175 386,2177 1738.5,2180.5 1808.5,2182.5 1473.5,2183.5 1513.5,2186.5 1678.5,2187.5 3586.26,2194.9 3727.68,2194.9 3869.1,2194.9 4434.79,2194.9 4576.21,2194.9 1622.5,2207.5 794,2209 451,2219 4347.85,2221.32 1681.5,2222.5 854,2239 3452.26,2241.96 3549.76,2241.96 3642.31,2241.81 3158.08,2242.95 3258.95,2242.74 3359.82,2242.52 4275,2250 1627.5,2254.5 3798.39,2265.61 4505.5,2265.61 409,2268 229,2283 1396.5,2284.5 4423.99,2296.19 1430,2300 1038.98,2312.72 1535.5,2313.5 1495,2320 3734.57,2329.38 3868.26,2329.49 3664.4,2329.88 3802.08,2329.72 3303.42,2336.32 4151.94,2336.32 4576.21,2336.32 175,2344 3610,2344 4316,2344 2957.41,2354.42 3062.19,2357.63 2849.86,2358.55 1495,2360 3923.67,2365.91 4499.81,2371.38 4410,2380 1501.5,2392.5 1400,2395 1465,2395 2815.46,2395.01 2921.56,2394.86 1198.5,2396.5 978.5,2402.5 1013.5,2402.5 545.7,2407.03 3374.13,2407.03 3261.18,2418.36 1786,2419 1750,2421 2664,2421 1318.5,2428.5 4472.64,2428.88 1701.55,2437.02 1373.5,2442.5 4575.63,2446.57 1498.5,2447.5 2815.8,2448.42 1428.5,2452.5 2780,2453 4097.57,2453.95 4139.79,2454.11 4183.62,2453.97 4229.16,2454.14 1176.5,2457.5 4355.92,2470.14 1944,2474 427,2477 1660.17,2478.66 1339.5,2479.58 634,2489 1212.5,2489.5 3461.91,2489.83 332,2495 4624.91,2495.23 3262,2496 1922,2497 3436.41,2500.56 191,2503 4544.67,2503.44 2414,2515 1624.86,2516.08 4356.5,2520.68 4223,2522 1058,2528 4698.6,2538.27 2816,2544 4415,2544 4307,2546 114,2554 2078,2554.5 2867.33,2557.09 1282.5,2562.5 599,2563 2768,2565 3262,2566 1488.5,2568.5 1386.5,2569.5 3993.95,2570.26 4357.08,2571.22 2650.9,2573.41 4614.17,2574.21 2599.92,2575.92 2080,2578 1099,2579 3293.45,2579.1 779,2589 2045,2594 699,2599 2354,2600 4150.82,2602.24 1530.42,2602.56 2510,2605 3605.37,2605.04 4698.6,2606.65 3635.75,2608.1 2814,2618 4576.21,2619.16 2705,2622 4303,2622 1448.25,2627.07 1219,2634 3262,2636 1159,2639 3106.77,2640.74 3668,2643 3700,2643 3732,2643 3764,2643 3796,2643 3828,2643 3860,2643 3892,2643 3926,2643 2021,2646 2721,2646 2872.38,2647.63 4214,2650 4624.6,2652.87 1286.05,2667.62 185,2669 2814,2672 2965.71,2672.25 1947,2673 1399.48,2674.2 3668,2675 3700,2675 3732,2675 3764,2675 3796,2675 3828,2675 3860,2675 3892,2675 3926,2675 4698.6,2675.04 3300,2682 1630,2690 1872.92,2689.98 2452,2690 4505.5,2689.87 4355.67,2690.91 2643,2693 2173,2706 3085.63,2705.54 3262,2706 1946,2712 2766,2714 2624.5,2718 4307,2718 764,2719 4397,2719 3001.99,2721.17 3110.11,2722.8 1675,2730 2943,2733 4631.55,2735.01 2816,2736 2883,2737 2159,2739 3668,2739 3700,2739 3732,2739 3764,2739 3796,2739 3828,2739 3860,2739 3892,2739 3926,2739 4355.67,2742.03 1314,2743 1381.77,2742.87 4698.6,2743.42 593,2745 2290,2745 2639.73,2745.4 2677.35,2745.22 2708.55,2745.4 1244,2746 1874.51,2746.97 724,2749 3369,2749.19 1183.06,2752.21 2777,2761 4576.21,2760.58 2212.27,2764.38 3668,2771 3700,2771 3732,2771 3764,2771 3796,2771 3828,2771 3860,2771 3892,2771 3926,2771 2513.73,2773 1207.4,2775.88 3262,2776 2683.23,2788.01 4399,2788 2642.4,2788.73 3369,2793.95 2544.76,2797.56 4307,2798 2614.56,2798.94 2865.39,2803.14 2910.29,2803.07 2955.34,2803.07 3004.38,2803.07 3700,2803 3732,2803 3764,2803 3796,2803 3828,2803 3860,2803 3892,2803 3926,2803 4355.98,2803.38 2788,2807 2209.03,2808.59 123,2810 2092,2810 4698.6,2811.81 2243,2817 4633.44,2817.78 2825.46,2819.72 2483,2826 2552.06,2827.35 2600.89,2833.23 307,2836 457,2836 3700,2837 3732,2837 3764,2837 3796,2837 3828,2837 3860,2837 3892,2837 3926,2837 2445,2842 3371.47,2842.11 2372.6,2844.29 2092,2845 3262,2846 1494.73,2862.32 629,2864 2308.5,2864.13 1715,2865 2788,2868 3298,2870 2247,2871 3668,2871 3700,2871 3732,2871 3764,2871 3796,2871 3828,2871 3860,2871 3892,2871 3926,2871 3501.94,2871.79 4357.58,2874.39 2398.71,2875.84 2027,2880 4698.6,2880.19 2337.29,2884.86 3391,2886 2821,2887 2933.21,2888.1 1770,2890 3459,2890 4230,2890 1931,2893 2469.5,2893 1974,2897 2158,2898 2274,2899.5 192.15,2902.01 899.25,2902.01 4576.21,2902.01 3487.24,2902.97 2209,2904 3668,2905 3700,2905 3764,2905 3796,2905 3828,2905 3926,2905 1404,2909 2497,2913 2088,2915 3262,2916 4225,2920 4421,2921 1679,2924 4307,2926 2897.49,2926.75 1496,2931 3300.84,2933.29 1930,2935 2959,2937 4004.8,2936.79 4357.58,2937.38 2812,2938 714,2939 2026,2943 1177.41,2943.93 3004.55,2948.91 4698.6,2948.58 1755,2950 1830,2950 2386.84,2951.25 2345.57,2951.56 1985,2955 2778,2958 4624.6,2958.05 4489.76,2961.31 2084,2964 3055.53,2967.5 3372,2970 2412,2972 2496,2972 121.44,2972.72 262.86,2972.72 2554,2974 2814,2980 2037,2981 4566.23,2983.75 3323,2986 2679,2989 4307,2990 1361,2991 1495.8,2992.37 2347.39,2994.42 3408,2994 3447,2994 2390,2997.58 4358.77,2997.7 1104,2999 2089,2999 1580,3000 1779,3004 4270.42,3006.85 1428,3009 2760.18,3013.46 1294,3014 4698.6,3016.96 2816,3020 2074,3028 1895,3030 2624,3039 3384,3042 3448,3042 3490,3042 3532,3042 3588,3042 899.25,3043.43 2388.86,3043.44 3161.99,3043.43 4576.21,3043.43 2345.76,3044.23 3338,3044 4042,3044 4072,3044 4230.11,3044.05 4282.7,3044.94 4355.43,3045.01 3280,3046 2308,3050 1371,3055 4462.2,3056.58 1014,3059 1816.9,3058.84 4507.51,3059.28 1496.62,3060.89 1620,3061 1719,3061 2546,3062 2822,3062 4414,3062 1557.2,3062.81 2432,3064 2486,3064 2768,3064 2689.56,3064.66 2344.57,3082.98 1154,3084 4698.6,3085.35 2390.44,3086.54 1899.87,3090.48 4620.39,3090.51 2037,3103 1529,3109 2694,3109 1637,3110 2239,3113 4173.07,3113.42 262.86,3114.14 828.54,3114.14 2814,3114 3374.13,3114.14 1833,3117 2558.88,3119.29 3272.75,3118.8 4233.75,3122.56 4321.03,3126.72 2275,3128 1993,3130 2394.4,3141.58 704,3144 396,3146 2334.29,3146.76 622,3150 3339.73,3150.69 2780,3154 4698.6,3153.73 3472.47,3155.89 1759,3159 2693,3159 123,3160 1155,3160 4173.91,3160.8 3409.44,3166.27 1439,3169 2334.7,3178.47 2396.47,3180.75 2454.89,3184.85 3008,3186 4311.05,3186.56 2059.58,3189.29 4237.08,3194.87 4369.23,3199.99 4451.48,3201.02 4079.73,3202.96 1759,3204 984,3211 1842,3212 4619.57,3217.56 2398.54,3222 4698.5,3222.11 2656.68,3230.09 4196.85,3232.93 4012.58,3233.96 4122.84,3234.21 4308.06,3235.07 2822.44,3238.39 4431.47,3240.26 4530.48,3242.6 3711.69,3245.89 4076.36,3247.21 2317.51,3247.95 2416.13,3249.13 3458.38,3253.77 1252.81,3255.56 1959.91,3255.56 2525.6,3255.56 3091.28,3255.56 872,3257 501,3262 3786,3262.29 284,3264 4404.73,3266.72 4534.77,3270.15 4435.89,3275.35 4079.48,3278.53 1825,3285 4013.8,3285.49 919,3289 699,3294 1749,3299 2224.5,3302 3396.83,3302.72 3488.36,3304.77 4533.72,3305.46 999,3314 192.15,3326.27 2596.31,3326.27 3020.57,3326.27 3161.99,3326.27 3303.42,3326.27 3444.84,3326.27 3562.94,3330.99 4611.11,3331.35 2814.68,3332.72 3784.62,3334.51 4500.22,3341.21 4387.62,3342.44 4460.34,3341.58 4533.06,3341.58 4314.9,3343.29 4242.19,3344.15 3526.06,3344.52 3718.79,3349.16 3278.62,3359.09 1294,3364 3426.26,3367.71 3853.81,3369.62 4513.03,3372.78 4304.72,3374.33 4408.87,3373.55 4067.56,3374.91 4200.56,3375.1 4004.84,3376.41 1425,3381 2828.02,3382.13 2665.18,3382.6 1574,3384 1954,3384 3781.92,3384.47 2525.34,3386.32 1839,3389 121.44,3396.98 828.54,3396.98 2384.18,3396.98 1684,3407 638,3408 944,3409 3286.49,3409.68 288,3412 507,3413 1214,3414 4300.65,3420.98 4402.48,3421.37 4504.32,3421.76 4198.82,3423.69 1415,3434 3760.65,3436.45 1054,3449 3352.44,3452.02 3583.65,3452.02 3504.96,3453.52 3546.55,3453.52 3399.66,3454.65 1736,3460 2313.47,3467.69 3303.42,3467.69 3444.84,3467.69 2434.79,3474.54 1244,3504 1584,3504 2034,3504 123,3510 964,3514 1024,3514 1909,3514 1969,3519 854,3534 1344,3534 3798.39,3538.4 4222.66,3538.4 4364.08,3538.4 1484,3539 1669,3539 2186.67,3542.97 1174,3551 2113,3555 4673,3560 3147,3563 1249,3564 1574,3564 1725,3567 2714,3594 3015,3604 3869.1,3609.11 4151.94,3609.11 2460,3614 2404,3618 1809,3619 2139,3619 2529,3619 1194,3640 579,3641 2047,3649 2374,3649 2704,3654 3319,3654 1711,3661 2334,3664 3257,3666 121.44,3679.82 404.28,3679.82 687.12,3679.82 828.54,3679.82 1413,3680 3656.97,3679.82 4364.08,3679.82 1302,3688 1494,3699 1124,3704 2947,3708 3986,3717 3127,3719 3854,3721 4046,3742 3167,3748 3407,3749 616.41,3750.53 3586.26,3750.53 913,3777 1029,3779 2746,3803 123,3810 423,3810 723,3810 1023,3810 1323,3810 1673,3810 2023,3810 2273,3810 2573,3810 2873,3810 3173,3810 3473,3810 3773,3810 4073,3810 4373,3810 4673,3810 262.86,3821.24 545.7,3821.24 1535.65,3821.24 2384.18,3821.24 3656.97,3821.24 3939.81,3821.24 4222.66,3821.24 4505.5,3821.24
  other v2: 1349.5,2041 1349.45,2072.09 1232.5,2233.5 2240.51,2306.5 1272.5,2337.5 2270.8,2386.1 2180,2395 2264,2433 2221,2445 3606,3245 3624,3245 3642,3245 3606,3263 3624,3263 3642,3263 3916,3264 3934,3264 3952,3264 3606,3281 3624,3281 3642,3281 3916,3282 3934,3282 3952,3282 3916,3300 3934,3300 3952,3300
GND_L: D1.1 J1.1 J1.2 L36.1 R257.1 | length 903.1
  Top w20: J1.1@3942,275.78 4040.43,275.78 4130.98,366.33 J1.2@4130.98,401.76 4130.98,434 4287.58,590.61 D1.1@4287.58,639 4287.58,679 4308.53,699.94 L36.1@4474,699.94 4574,699.94 R257.1@4574,703.88
GPIO0: R124.2 R126.2 U1.D7 | length 324.9
  Top w5: v2(2276.5,2202.03) 2276.64,2202.03 2276.64,2218.17 U1.D7@2276.79,2218.17
  Inner Layer 3 w4: v2(2276.5,2202.03) 2300.54,2178 2328,2178
  Inner Layer 3 w5: 2328,2178 2365,2215 2385,2215 2395,2225 v1(2485,2225)
  Bottom w5: v1(2485,2225) 2496,2236 R124.2@2517,2236 R126.2@2517,2202
GPIO11: TP249.1 UA4.44 | length 288.5
  Top w5: UA4.44@3974.2,2711.01 3999.82,2711.01 4014.28,2725.47 4016.06,2725.47 4061.86,2771.27 4186.53,2771.27 4221.35,2736.45 4220,2735.1 TP249.1@4220,2735
GPIO12: TP250.1 UA4.45 | length 69.8
  Top w5: UA4.45@3974.2,2726.76 3993.38,2726.76 v1(4006.79,2740.17)
  Bottom w5: TP250.1@3980,2745 3980,2742.58 4006.79,2742.58 v1(4006.79,2740.17)
GPIO13: TP251.1 UA4.46 | length 80.2
  Top w5: UA4.46@3974.2,2742.5 3974.2,2741.45 3984.7,2741.45 4006.28,2763.03 v1(4005.08,2764.23)
  Bottom w5: TP251.1@3980,2790 3979.83,2789.83 4005.25,2764.4 v1(4005.08,2764.23)
GPIO19: TP246.1 UA4.54 | length 161.4
  Top w5: UA4.54@3974.2,2868.49 3974.2,2870.25 3985.41,2870.25 4006.15,2849.5 4098.5,2849.5 4104,2855 4122,2855 TP246.1@4122,2856
HOLD: R151.1 U18.7 | length 59.1
  Top w5: R151.1@2980,3452 2980,3414 2987,3407 U18.7@2987,3395.8
I2C_SCL_CODEC: JP2.10 R909.2 | length 86.1
  Bottom w5: JP2.10@626,1504 636,1494 R909.2@636,1422
I2C_SCLK: R53.2 R909.1 U1.U14 U9.6 | length 3683.7
  Top w5: v1(664,1384) 713,1384 885.5,1556.5 1931.96,1556.5 1932.01,1556.56 1936.56,1556.56 2156.69,1776.69 2156.69,1845.69 2164,1853 2164,1856.26 U1.U14@2168.21,1856.26
  Bottom w5: U9.6@277.49,2615 R53.2@231,2615 218,2615 134,2531 134,2019.03 125,2010.03 125,1800.01 134,1791.01 134,1407 169.5,1371.5 331.5,1371.5 389,1314 614,1314 640,1340 640,1382 R909.1@636,1386 662,1386 v1(664,1384)
I2C_SD: R52.2 R910.1 U1.T14 U9.5 | length 3511.6
  Top w5: v1(299,1404) 337,1366 710,1366 891.5,1547.5 1935.69,1547.5 1935.74,1547.56 1942.56,1547.56 2165.69,1770.69 2165.69,1836.19 2186.31,1856.81 U1.T14@2186.31,1874.36
  Bottom w5: U9.5@277.49,2565 274.49,2568 230,2568 R52.2@231,2569 189,2569 144,2524 144,2016.26 135,2007.26 135,1802.74 237.74,1700 240,1700 261,1679 R910.1@262,1679 284,1657 284,1419 v1(299,1404)
I2C_SDA_CODEC: JP2.1 R910.2 | length 75
  Bottom w5: JP2.1@226,1604 R910.2@226,1679
I2SSCLK: JP2.6 R902.2 | length 70
  Bottom w5: R902.2@426,1434 JP2.6@426,1504
I2SSDI: JP2.2 R906.2 | length 71.4
  Bottom w5: R906.2@225,1433 225,1503 JP2.2@226,1504
I2SSDO: JP2.4 R904.2 | length 71
  Top w5: R904.2@326,1433 JP2.4@326,1504
I2SWS: JP2.3 R903.2 | length 71
  Top w5: JP2.3@326,1604 R903.2@326,1675
JTAGRST_N: D47.1 J13.11 R472.2 R897.2 R899.1 RC1.1 U627.2 | length 3260.2
  Top w5: v1(316,2194) 374,2194 654,2474 654,3379 1024.03,3750.97 1028.25,3750.97 1031.27,3754 1532,3754 v1(1539,3761) ; R472.2@1587,3139 1587,3207 J13.11@1589,3209
  Bottom w5: RC1.1@265,2277.59 266.2,2278.8 RC1.1@266.2,2288 ; U627.2@266.2,2338.68 RC1.1@266.2,2288 ; v1(316,2194) R899.1@316,2220 D47.1@316,2254 316,2287 R897.2@315,2288 RC1.1@266.2,2288 ; v1(1539,3761) 1539,3760 1528,3749 1528,3280 1589,3219 J13.11@1589,3209
LANLED1: D11.1 R166.1 | length 55.2
  Top w4: R166.1@1618,3572 1618,3621.51 1619.27,3622.78 D11.1@1623.21,3622.78
LANLED2: D10.1 R165.1 | length 49.2
  Top w4: R165.1@1933,3578 1933,3621.55 1934.23,3622.78 D10.1@1938.17,3622.78
LANLED3: D9.1 R163.1 | length 47.8
  Top w4: R163.1@2249,3579 2249,3622.59 2249.19,3622.78 D9.1@2253.13,3622.78
LANLED4: D8.1 R160.1 | length 46.8
  Top w4: R160.1@2564,3580 2564,3622.62 2564.16,3622.78 D8.1@2568.1,3622.78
